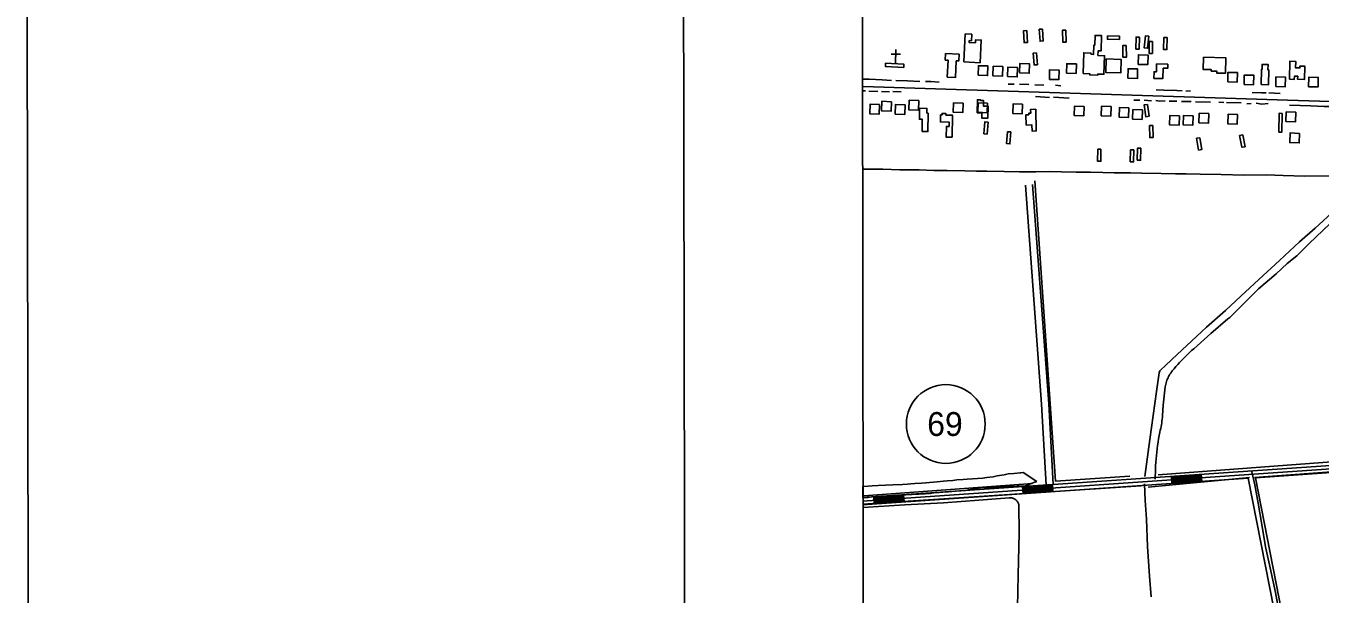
# Model space of a CAD drawing. Extents: x 3324125 to 3362000, y 600753 to 626151.
# Drawn here: x 3324708 to 3330131, y 619849 to 622228 of the extents above; entities that cross this region are included whole.
import ezdxf

# ---------------------------------------------------------------- set-up
doc = ezdxf.new("R2010")
doc.units = 0
for name, color, linetype in [('G-ANNO-NPLT', 7, 'Continuous'), ('V-ANNO-SYMB', 7, 'Continuous'), ('V-BLDG-OTLN', 7, 'Continuous'), ('V-DTCH-CNTR', 7, 'Continuous'), ('V-GRID-FRAM', 7, 'Continuous'), ('V-ROAD-CNTR', 7, 'Continuous'), ('V-ROAD-IDEN', 7, 'Continuous'), ('V-SITE-OTLN', 7, 'Continuous'), ('V-SITE-VEGE', 7, 'Continuous'), ('V-TOPO-SHOR', 7, 'Continuous')]:
    doc.layers.add(name, color=color, linetype=linetype)

msp = doc.modelspace()

# ---------------------------------------------------------------- linework, layer by layer
at = {"layer": 'G-ANNO-NPLT'}
msp.add_lwpolyline([(3324750.5, 601336.7), (3361417.2, 601400.7), (3361375, 625567.3), (3324708.4, 625503.3)], close=True, dxfattribs=at)
at = {"layer": 'V-ANNO-SYMB'}
msp.add_lwpolyline([(3327499.6, 601966.6), (3360582.7, 602024.3), (3360542.7, 624940.8), (3327459.6, 624883.1), (3327499.6, 601966.6)], dxfattribs=at)
at = {"layer": 'V-BLDG-OTLN'}
for points in [[(3328638.1, 622077.4), (3328643.9, 622194.6), (3328670.9, 622193.2), (3328669.5, 622165.9), (3328660.4, 622166.4), (3328660, 622158.7), (3328686.7, 622157.4), (3328687.3, 622170), (3328710.6, 622168.8), (3328705.9, 622074)], [(3328902.1, 622208.5), (3328904.3, 622158.5), (3328890.3, 622157.9), (3328888.1, 622207.9)], [(3328968, 622214.8), (3328970.9, 622164.9), (3328957, 622164.1), (3328954, 622214)], [(3329065.9, 622210.6), (3329066.6, 622160.6), (3329052.6, 622160.4), (3329051.9, 622210.4)], [(3329137.3, 622028.6), (3329140.4, 622115.6), (3329170.8, 622114.5), (3329170.6, 622109.2), (3329181.7, 622108.8), (3329183, 622147.7), (3329186.6, 622147.5), (3329188, 622188.3), (3329215.1, 622187.4), (3329212.9, 622123.1), (3329200.1, 622123.5), (3329199.4, 622104.3), (3329227.3, 622103.4), (3329224.5, 622025.6), (3329199.2, 622026.5), (3329199, 622021.5), (3329165.3, 622022.7), (3329165.5, 622027.6)], [(3329239.6, 622186.2), (3329289.6, 622185.7), (3329289.5, 622171.7), (3329239.5, 622172.2)], [(3329318.6, 622146.5), (3329318.7, 622096.5), (3329304.7, 622096.5), (3329304.6, 622146.5)], [(3329358.9, 622130.9), (3329359.3, 622180.9), (3329373.3, 622180.8), (3329372.9, 622130.8)], [(3329412.7, 622184.5), (3329407.6, 622134.8), (3329393.7, 622136.2), (3329398.7, 622186)], [(3329428, 622163.1), (3329428.2, 622113.1), (3329414.2, 622113.1), (3329414, 622163.1)], [(3329489.4, 622178.9), (3329488.7, 622128.9), (3329474.7, 622129.1), (3329475.4, 622179.1)], [(3328606.4, 622081.6), (3328603.2, 622012.3), (3328568.5, 622013.9), (3328571.7, 622084.2), (3328559.8, 622084.7), (3328561.1, 622111.8), (3328618, 622109.2), (3328616.7, 622081.1)], [(3328942.9, 622115.3), (3328945.9, 622065.4), (3328931.9, 622064.6), (3328928.9, 622114.5)], [(3329234.1, 622089.7), (3329296.8, 622088), (3329295.2, 622031.3), (3329232.6, 622033.1)], [(3329368.6, 622066.9), (3329408.6, 622065.9), (3329409.5, 622105.9), (3329369.6, 622106.9)], [(3329641.6, 622097.1), (3329736, 622094.1), (3329733.9, 622029.6), (3329697.8, 622030.7), (3329698.1, 622038.4), (3329674.3, 622039.2), (3329674.5, 622044.8), (3329640, 622045.9)], [(3328310, 622071.8), (3328387.1, 622067.5), (3328386.3, 622054.1), (3328309.3, 622058.4)], [(3328697.7, 622021.2), (3328737.7, 622020.2), (3328738.7, 622060.2), (3328698.7, 622061.2)], [(3328759.9, 622019.1), (3328799.9, 622018.1), (3328800.9, 622058.1), (3328760.9, 622059.1)], [(3328821.5, 622015.5), (3328861.5, 622014.5), (3328862.5, 622054.5), (3328822.5, 622055.5)], [(3328871.7, 622031), (3328911.7, 622030), (3328912.7, 622069.9), (3328872.7, 622070.9)], [(3328996.2, 622004.1), (3329036.2, 622003.1), (3329037.2, 622043.1), (3328997.2, 622044.1)], [(3329068.4, 622029.8), (3329108.4, 622028.8), (3329109.4, 622068.8), (3329069.4, 622069.8)], [(3329325, 622008.8), (3329365, 622007.8), (3329366, 622047.8), (3329326, 622048.8)], [(3329472.5, 622050.9), (3329471.3, 622007.4), (3329434.3, 622008.4), (3329435, 622036.2), (3329444.5, 622035.9), (3329445.4, 622068.6), (3329492.4, 622067.3), (3329491.9, 622050.4)], [(3329743.4, 621993.4), (3329783.4, 621992.5), (3329784.3, 622032.5), (3329744.3, 622033.4)], [(3329883.4, 621982.4), (3329884.4, 622045.8), (3329887.4, 622045.7), (3329887.7, 622066.9), (3329912.3, 622066.6), (3329911.9, 622043.8), (3329915.4, 622043.7), (3329914.4, 621981.9)], [(3330002, 622004.6), (3330003.6, 622079.8), (3330028.5, 622079.3), (3330028, 622052.4), (3330045.9, 622052.1), (3330046, 622059.5), (3330066.6, 622059.1), (3330065.5, 622004.1), (3330036.4, 622004.7), (3330036.6, 622017.2), (3330022.6, 622017.5), (3330022.3, 622004.2)], [(3329812, 621982.3), (3329852, 621981.3), (3329853, 622021.3), (3329813, 622022.3)], [(3329944.7, 621974.3), (3329984.7, 621973.3), (3329985.6, 622013.3), (3329945.7, 622014.3)], [(3330082, 621973.3), (3330122, 621972.4), (3330123, 622012.4), (3330083, 622013.3)], [(3328285.2, 621898.5), (3328245.2, 621899.9), (3328243.8, 621859.9), (3328283.8, 621858.5)], [(3328334.7, 621910.8), (3328294.8, 621912.2), (3328293.3, 621872.3), (3328333.3, 621870.8)], [(3328391.9, 621897.5), (3328351.9, 621899), (3328350.5, 621859), (3328390.4, 621857.5)], [(3328449.4, 621915.2), (3328409.4, 621916.6), (3328407.9, 621876.6), (3328447.9, 621875.2)], [(3328488.3, 621863.3), (3328487.4, 621785.6), (3328463.3, 621785.9), (3328463.8, 621836.9), (3328451.5, 621837), (3328452, 621883.1), (3328482.9, 621882.8), (3328482.7, 621863.4)], [(3328634.8, 621904.9), (3328594.8, 621906.3), (3328593.3, 621866.3), (3328633.3, 621864.9)], [(3328693.9, 621864.1), (3328694.9, 621919.1), (3328707.3, 621918.9), (3328707.3, 621915.8), (3328720.4, 621915.5), (3328719.9, 621892.5), (3328739.2, 621892.2), (3328738.3, 621841.5), (3328713.2, 621841.9), (3328713.6, 621863.8)], [(3328737.6, 621904.7), (3328697.6, 621906.1), (3328696.2, 621866.2), (3328736.1, 621864.7)], [(3328884.2, 621899.9), (3328844.2, 621901.3), (3328842.8, 621861.3), (3328882.7, 621859.9)], [(3328939.3, 621878.9), (3328941.3, 621788.2), (3328923.6, 621787.8), (3328923, 621813.6), (3328899.2, 621813.1), (3328898.2, 621855.9), (3328909.9, 621856.1), (3328909.8, 621862.2), (3328918.1, 621862.4), (3328917.7, 621878.4)], [(3329141.9, 621891.1), (3329101.9, 621892.6), (3329100.4, 621852.6), (3329140.4, 621851.1)], [(3329255, 621890.6), (3329215.1, 621892.1), (3329213.6, 621852.1), (3329253.6, 621850.6)], [(3329329.7, 621884.7), (3329289.7, 621886.1), (3329288.2, 621846.2), (3329328.2, 621844.7)], [(3329386.4, 621876.5), (3329346.5, 621877.9), (3329345, 621837.9), (3329385, 621836.5)], [(3329407.2, 621899.2), (3329414, 621849.7), (3329400.1, 621847.8), (3329393.3, 621897.3)], [(3330028.9, 621866.7), (3329988.9, 621868.2), (3329987.5, 621828.2), (3330027.4, 621826.7)], [(3328561.9, 621854.9), (3328590.1, 621854.4), (3328588.5, 621762.2), (3328563.8, 621762.6), (3328564.6, 621807.5), (3328576, 621807.3), (3328576.3, 621825.4), (3328540, 621826), (3328540.5, 621855.6), (3328546.8, 621855.5), (3328546.9, 621861.8), (3328562, 621861.5)], [(3328740.1, 621825.1), (3328735.6, 621775.3), (3328721.7, 621776.6), (3328726.1, 621826.4)], [(3329541.2, 621852.1), (3329501.2, 621853.5), (3329499.8, 621813.5), (3329539.8, 621812.1)], [(3329598.4, 621852), (3329558.5, 621853.5), (3329557, 621813.5), (3329597, 621812)], [(3329664.1, 621860.7), (3329624.1, 621862.1), (3329622.6, 621822.2), (3329662.6, 621820.7)], [(3329784.9, 621856.8), (3329744.9, 621858.3), (3329743.5, 621818.3), (3329783.4, 621816.9)], [(3329957.8, 621783.2), (3329958.7, 621862.1), (3329971.3, 621861.9), (3329970.4, 621783.1)], [(3328834.9, 621783.8), (3328830.9, 621733.9), (3328817, 621735), (3328820.9, 621784.9)], [(3329430, 621811), (3329431.1, 621761), (3329417.1, 621760.7), (3329416, 621810.7)], [(3329626.7, 621759.8), (3329635.5, 621710.6), (3329621.7, 621708.2), (3329612.9, 621757.4)], [(3329806.9, 621771.3), (3329816.4, 621722.2), (3329802.7, 621719.6), (3329793.2, 621768.7)], [(3330044.7, 621778.2), (3330004.7, 621779.7), (3330003.3, 621739.7), (3330043.2, 621738.2)], [(3329212.5, 621711.3), (3329211.9, 621661.3), (3329197.9, 621661.5), (3329198.6, 621711.5)], [(3329350.7, 621708.5), (3329349.3, 621658.5), (3329335.3, 621658.9), (3329336.7, 621708.9)], [(3329380, 621715.7), (3329378.5, 621665.7), (3329364.5, 621666.1), (3329366, 621716.1)]]:
    msp.add_lwpolyline(points, close=True, dxfattribs=at)
at = {"layer": 'V-DTCH-CNTR'}
for points in [[(3330083, 621316.1), (3330348.1, 621568.2), (3330353.7, 621571.1), (3330378.6, 621581)], [(3329439.4, 620329.8), (3329440.9, 620372.4), (3329441.5, 620386.6), (3329442.3, 620400.8), (3329443.3, 620415), (3329444.6, 620429.1), (3329446, 620443.3), (3329447.6, 620457.4), (3329449.5, 620471.5), (3329451.6, 620485.6), (3329453.8, 620499.6), (3329456.3, 620513.6), (3329459, 620527.6), (3329461, 620535.2), (3329462.9, 620542.8), (3329464.5, 620550.5), (3329465.9, 620558.3), (3329467.1, 620566), (3329468.1, 620573.8), (3329468.9, 620581.7), (3329469.5, 620589.5), (3329469.8, 620597.4), (3329472.9, 620639.8), (3329481.7, 620717), (3329482.8, 620722.6), (3329484, 620728.1), (3329485.5, 620733.6), (3329487.1, 620739), (3329489, 620744.4), (3329491.1, 620749.6), (3329493.4, 620754.8), (3329495.9, 620759.9), (3329498.5, 620764.9), (3329501.4, 620769.8), (3329504.5, 620774.6), (3329507.7, 620779.3), (3329511.1, 620783.8), (3329514.7, 620788.2), (3329518.5, 620792.4), (3329526, 620801.4), (3329533.8, 620810.3), (3329541.6, 620819), (3329549.7, 620827.6), (3329557.9, 620836), (3329566.2, 620844.3), (3329574.7, 620852.5), (3329583.3, 620860.5), (3329592, 620868.3), (3329600.9, 620876), (3329672, 620940), (3329744.4, 621000.8), (3329751.8, 621007.2), (3329759, 621013.8), (3329766.1, 621020.5), (3329773, 621027.4), (3329779.7, 621034.5), (3329872.3, 621126.7), (3329946.8, 621190.3), (3329992.5, 621232.6), (3330032.5, 621265), (3330058.1, 621290.4), (3330083, 621316.1)], [(3329844.3, 620360.5), (3329857.1, 620307), (3329870.9, 620229.7), (3329886.2, 620140.4), (3329902.4, 620046.7), (3329920.9, 619959.3), (3329943.7, 619855.6), (3329960.3, 619763.9), (3329979.9, 619659.5), (3329998.9, 619576.9), (3330013.2, 619513.9), (3330033.6, 619398.7), (3330049, 619317.7), (3330073.6, 619184.1), (3330091.3, 619088.4), (3330115.7, 618974), (3330126.9, 618919.7), (3330132.5, 618888.2)], [(3328862.6, 619794), (3328865, 619927.8), (3328869.4, 620105.4), (3328868.5, 620220.9), (3328868.1, 620223.6), (3328867.4, 620226.2), (3328866.6, 620228.7), (3328865.5, 620231.2), (3328864.3, 620233.6), (3328862.9, 620235.9), (3328861.4, 620238.1), (3328859.6, 620240.1), (3328857.8, 620242), (3328855.8, 620243.8), (3328853.6, 620245.4), (3328851.3, 620246.9), (3328849, 620248.2), (3328846.5, 620249.3), (3328844, 620250.2), (3328841.4, 620250.9), (3328838.8, 620251.4), (3328836.1, 620251.7), (3328833.4, 620251.8), (3328830.8, 620251.7), (3328828.1, 620251.4), (3328701.4, 620242.7), (3328552.4, 620231.7), (3328390.6, 620222.4), (3328215.3, 620211.8)]]:
    msp.add_lwpolyline(points, dxfattribs=at)
at = {"layer": 'V-GRID-FRAM'}
msp.add_lwpolyline([(3328210, 624318.2), (3328233.8, 606134.5), (3359834, 606189.7), (3359794.3, 624373.3), (3328210, 624318.2)], dxfattribs=at)
at = {"layer": 'V-ROAD-CNTR'}
for p, q in [((3329632.3, 620350.5), (3329634.4, 620320.5)), ((3328884.1, 620299), (3328886.2, 620269)), ((3329008.8, 620307.5), (3329010.9, 620277.6)), ((3329507.6, 620341.9), (3329509.7, 620311.9)), ((3328260.6, 620256.1), (3328262.6, 620226.1)), ((3328385.3, 620264.6), (3328387.3, 620234.7))]:
    msp.add_line(p, q, dxfattribs=at)
for points in [[(3332722.7, 621829.2), (3331917.1, 621857.3), (3329994.2, 621916.4), (3328216, 621974)], [(3328895.7, 621561.6), (3328963.9, 620643.8), (3328982.6, 620305.7)], [(3328925.6, 621563.9), (3328993.9, 620645.7), (3329012.5, 620307.8)], [(3328212.9, 620237.7), (3330156, 620371.5), (3332442.6, 620541.1)], [(3329012.5, 620307.8), (3330154.9, 620386.4), (3332441.5, 620556.1)], [(3329859.2, 620336), (3330157.1, 620356.5), (3331715.9, 620472.2)], [(3328212.9, 620252.8), (3329008.8, 620307.5)], [(3328213, 620222.7), (3329829, 620333.9)], [(3328884.3, 620296), (3329009, 620304.6)], [(3328884.5, 620293), (3329009.2, 620301.6)], [(3328884.7, 620290), (3329009.4, 620298.6)], [(3328884.9, 620287), (3329009.6, 620295.6)], [(3329507.8, 620338.9), (3329632.5, 620347.5)], [(3329508, 620335.9), (3329632.7, 620344.5)], [(3329508.2, 620332.9), (3329632.9, 620341.5)], [(3329508.4, 620329.9), (3329633.2, 620338.5)], [(3329508.7, 620326.9), (3329633.4, 620335.5)], [(3329508.9, 620323.9), (3329633.6, 620332.5)], [(3329509.1, 620320.9), (3329633.8, 620329.5)], [(3329509.3, 620317.9), (3329634, 620326.5)], [(3329509.5, 620314.9), (3329634.2, 620323.5)], [(3329829, 620333.9), (3330027.3, 619328.5)], [(3329859.2, 620336), (3330007.1, 619586.3)], [(3328260.8, 620253.1), (3328385.5, 620261.6)], [(3328261, 620250.1), (3328385.7, 620258.7)], [(3328261.2, 620247.1), (3328385.9, 620255.7)], [(3328261.4, 620244.1), (3328386.1, 620252.7)], [(3328261.6, 620241.1), (3328386.3, 620249.7)], [(3328261.8, 620238.1), (3328386.5, 620246.7)], [(3328262, 620235.1), (3328386.7, 620243.7)], [(3328262.2, 620232.1), (3328386.9, 620240.7)], [(3328885.1, 620284), (3329009.8, 620292.6)], [(3328885.3, 620281), (3329010, 620289.6)], [(3328885.5, 620278), (3329010.2, 620286.6)], [(3328885.7, 620275), (3329010.5, 620283.6)], [(3328886, 620272), (3329010.7, 620280.6)], [(3328262.4, 620229.1), (3328387.1, 620237.7)]]:
    msp.add_lwpolyline(points, dxfattribs=at)
at = {"layer": 'V-ROAD-IDEN'}
msp.add_circle((3328562.4, 620561.1), 165, dxfattribs=at)
at = {"layer": 'V-SITE-OTLN'}
for p, q in [((3328372.9, 622109.3), (3328332.9, 622110.3)), ((3328351.9, 622069.8), (3328353.4, 622129.8))]:
    msp.add_line(p, q, dxfattribs=at)
at = {"layer": 'V-SITE-VEGE'}
for p, q in [((3328806.7, 620348.5), (3328824.2, 620352.1)), ((3328824.2, 620352.1), (3328847.7, 620354.2)), ((3328847.7, 620354.2), (3328874.4, 620356.8)), ((3328874.4, 620356.8), (3328877.1, 620356.8)), ((3328877.1, 620356.8), (3328885.9, 620358.6)), ((3328885.9, 620358.6), (3328943.1, 620320)), ((3328215.2, 620299.8), (3328237.6, 620301.1)), ((3328215.3, 620251.7), (3328215.2, 620299.8)), ((3328237.6, 620301.1), (3328253.7, 620302.4)), ((3328253.7, 620302.4), (3328279, 620303.1)), ((3328279, 620303.1), (3328339.8, 620306)), ((3328339.8, 620306), (3328380.7, 620308)), ((3328380.7, 620308), (3328401.5, 620309.7)), ((3328401.5, 620309.7), (3328415.7, 620311)), ((3328415.7, 620311), (3328432.3, 620311.4)), ((3328432.3, 620311.4), (3328460.4, 620313)), ((3328460.4, 620313), (3328479.3, 620314.3)), ((3328479.3, 620314.3), (3328526.7, 620318.6)), ((3328526.7, 620318.6), (3328552.5, 620321.2)), ((3328552.5, 620321.2), (3328567.7, 620322.9)), ((3328567.7, 620322.9), (3328591.6, 620324.6)), ((3328591.6, 620324.6), (3328608.2, 620326.8)), ((3328608.2, 620326.8), (3328634.9, 620328.9)), ((3328634.9, 620328.9), (3328652.4, 620330.2)), ((3328652.4, 620330.2), (3328717.3, 620334.4)), ((3328743.3, 620295.1), (3328706.5, 620293.9)), ((3328717.3, 620334.4), (3328734.8, 620337)), ((3328734.8, 620337), (3328760.1, 620340.5)), ((3328763.5, 620296.3), (3328743.3, 620295.1)), ((3328760.1, 620340.5), (3328777.2, 620343.6)), ((3328776.4, 620296.7), (3328763.5, 620296.3)), ((3328793.9, 620298), (3328776.4, 620296.7)), ((3328777.2, 620343.6), (3328806.7, 620348.5)), ((3328803.1, 620298.8), (3328793.9, 620298)), ((3328817.4, 620298.7), (3328803.1, 620298.8)), ((3328828.9, 620299.1), (3328817.4, 620298.7)), ((3328849.1, 620299.5), (3328828.9, 620299.1)), ((3328862, 620300.3), (3328849.1, 620299.5)), ((3328874.5, 620300.7), (3328862, 620300.3)), ((3328884.6, 620300.6), (3328874.5, 620300.7)), ((3328896.6, 620302.4), (3328884.6, 620300.6)), ((3328907.6, 620306.4), (3328896.6, 620302.4)), ((3328919.6, 620311.4), (3328907.6, 620306.4)), ((3328935.3, 620317.3), (3328919.6, 620311.4)), ((3328943.1, 620320), (3328935.3, 620317.3)), ((3328237.7, 620253.2), (3328215.3, 620251.7)), ((3328251.6, 620255.5), (3328237.7, 620253.2)), ((3328270.9, 620257.2), (3328251.6, 620255.5)), ((3328284.2, 620257.5), (3328270.9, 620257.2)), ((3328306.3, 620257.4), (3328284.2, 620257.5)), ((3328349.1, 620259.4), (3328306.3, 620257.4)), ((3328366.6, 620261.2), (3328349.1, 620259.4)), ((3328394.3, 620264.2), (3328366.6, 620261.2)), ((3328450, 620267.1), (3328394.3, 620264.2)), ((3328463.3, 620268.4), (3328450, 620267.1)), ((3328476.2, 620268.7), (3328463.3, 620268.4)), ((3328496.5, 620270.4), (3328476.2, 620268.7)), ((3328512.1, 620272.6), (3328496.5, 620270.4)), ((3328534.2, 620274.3), (3328512.1, 620272.6)), ((3328549.9, 620276.1), (3328534.2, 620274.3)), ((3328573.4, 620277.8), (3328549.9, 620276.1)), ((3328603.3, 620280.3), (3328573.4, 620277.8)), ((3328625.4, 620281.6), (3328603.3, 620280.3)), ((3328644.3, 620283.3), (3328625.4, 620281.6)), ((3328657.6, 620285), (3328644.3, 620283.3)), ((3328672.4, 620287.7), (3328657.6, 620285)), ((3328693.1, 620291.7), (3328672.4, 620287.7)), ((3328706.5, 620293.9), (3328693.1, 620291.7))]:
    msp.add_line(p, q, dxfattribs=at)
at = {"layer": 'V-TOPO-SHOR'}
for p, q in [((3328823.2, 621984), (3328848.1, 621983.7)), ((3328870.8, 621983.5), (3328910.6, 621982.5)), ((3328935.5, 621981.9), (3328973.2, 621980.5)), ((3329022.1, 621979.2), (3329044.1, 621976.8)), ((3328213.1, 621956.4), (3328225.5, 621956.1)), ((3328240.4, 621954.9), (3328277.3, 621953.9)), ((3328292.6, 621953.6), (3328325.8, 621952.2)), ((3328341.1, 621952.7), (3328375.5, 621952.2)), ((3328937.5, 621932.6), (3328996.8, 621928.8)), ((3329013.8, 621929), (3329078.9, 621926.1)), ((3329568, 621954.5), (3329587.1, 621955.8)), ((3329916.1, 621947.4), (3329963.4, 621944.9)), ((3329349.9, 621917.7), (3329375.2, 621917)), ((3329393.8, 621916.8), (3329424.5, 621914.5)), ((3329498.3, 621913), (3329530.6, 621913.2)), ((3329550.1, 621911.7), (3329590.7, 621911.5)), ((3329608.9, 621910.4), (3329671.1, 621908.8)), ((3329705.9, 621908.6), (3329727.1, 621908)), ((3329737.8, 621907.6), (3329800, 621905.6)), ((3329823.6, 621902), (3329842.3, 621902.6)), ((3328935.2, 621580), (3329022.1, 620322.1)), ((3329855.6, 620337.4), (3331716.9, 620470.4)), ((3329451.6, 620347.7), (3330791.4, 620449.9)), ((3328214.2, 620225), (3329380.1, 620301.7)), ((3328219.3, 620260.7), (3328925, 620311.9)), ((3329022.1, 620322.1), (3329334, 620342.6)), ((3329410.7, 620296.5), (3329835.2, 620337.4))]:
    msp.add_line(p, q, dxfattribs=at)
for points in [[(3328213, 622005.5), (3328241.4, 622004.7), (3328295.7, 622001.7), (3328335.4, 621999.9)], [(3328353.2, 621999.7), (3328402.3, 621998.3), (3328453.9, 621995.8)], [(3328477.9, 621995.6), (3328500.1, 621994.9), (3328533.9, 621993.1)], [(3329444.1, 621960.2), (3329475.7, 621959.2), (3329529.6, 621957.9), (3329553.1, 621956.4)], [(3329845.7, 621949), (3329885.6, 621947.6), (3329904.1, 621947.8)], [(3329442.8, 621915), (3329459.3, 621912.5), (3329480.9, 621913.7)], [(3329862.2, 621903.9), (3329886.6, 621900.2), (3329913.1, 621902.7)], [(3330002.7, 621896.3), (3330091.8, 621893.8), (3330146.9, 621890.9), (3330167.7, 621890.4)], [(3328213.5, 621627.9), (3328245, 621627.6), (3328298, 621627.9), (3328370.3, 621625.5), (3328450.5, 621625.7), (3328512.8, 621622.8), (3328568.4, 621622.4), (3328642.2, 621621.8), (3328690.7, 621620.3), (3328734, 621620.2), (3328806.7, 621617.8), (3328871.6, 621616.8), (3328939.9, 621616.9), (3328995.4, 621618.4), (3329047.3, 621617.6), (3329108.4, 621615.5), (3329168.9, 621615.9), (3329220, 621613.7), (3329267.3, 621612.5), (3329335.6, 621612.2), (3329383, 621611.8), (3329464.3, 621610.6), (3329524.3, 621608.7), (3329569.4, 621608.3), (3329627.6, 621606.9), (3329716, 621606), (3329811.9, 621603.7), (3329905.9, 621604.8), (3329976, 621601.5), (3330066.3, 621598.8), (3330197.2, 621599.8)], [(3330195.6, 621458.8), (3330109.1, 621381.5), (3330044.5, 621323.5), (3329960.5, 621245.8), (3329874.1, 621166), (3329798.7, 621097.1), (3329734.1, 621036.6), (3329654.6, 620966.4), (3329634, 620947.2)], [(3329634, 620947.2), (3329510.8, 620832.8), (3329479.6, 620803.2), (3329465.1, 620789.3), (3329459.1, 620783.8), (3329455.9, 620775.9), (3329444.6, 620697.1), (3329417.4, 620496.1), (3329396.4, 620341.7)], [(3329394.6, 620310.6), (3329397.9, 620240.6), (3329402.5, 620162.1), (3329407.4, 620047.8), (3329415.3, 619923.4), (3329422.3, 619837)]]:
    msp.add_lwpolyline(points, dxfattribs=at)

# ---------------------------------------------------------------- texts
at = {"layer": 'V-ROAD-IDEN'}
msp.add_text('69', height=100, rotation=359.9873, dxfattribs=at).set_placement((3328484.4, 620511.1))

doc.saveas('drawing.dxf')
